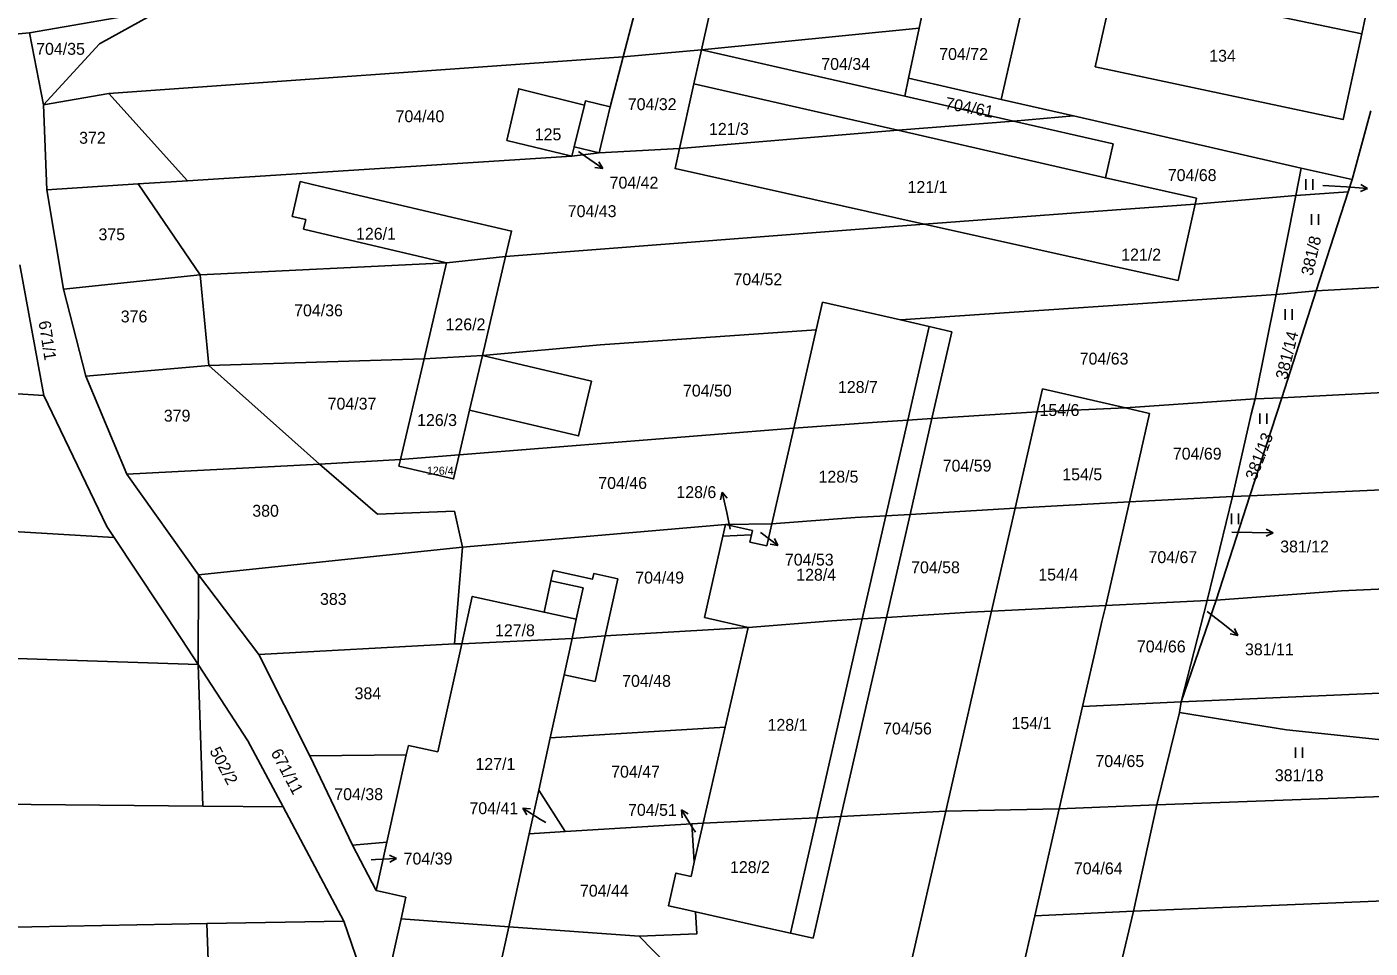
# Model space of a CAD drawing. Extents: x -747333 to -743907, y -1134120 to -1130051.
# Drawn here: x -746331.7 to -746140.1, y -1132458.3 to -1132327 of the extents above; entities that cross this region are included whole.
import ezdxf

# ---------------------------------------------------------------- set-up
doc = ezdxf.new("R2010")
doc.units = 0
for name, color, linetype in [('Hranice parcel', 7, 'Continuous'), ('Parcelní čísla', 7, 'Continuous'), ('Pop  PČ popisy', 7, 'Continuous'), ('Vnitřní kresba', 7, 'Continuous'), ('Značky kultur', 7, 'Continuous')]:
    doc.layers.add(name, color=color, linetype=linetype)

msp = doc.modelspace()

# ---------------------------------------------------------------- linework, layer by layer
at = {"layer": 'Hranice parcel'}
for p, q in [((-746243.49, -1132318.9), (-746246.67, -1132331.25)), ((-746204.45, -1132327.15), (-746203.36, -1132322.01)), ((-746312.67, -1132324.59), (-746331.35, -1132327.82)), ((-746331.35, -1132327.82), (-746338.47, -1132328.52)), ((-746329.35, -1132338.1), (-746331.35, -1132327.82)), ((-746235.51, -1132330.26), (-746204.45, -1132327.15)), ((-746205.97, -1132334.3), (-746204.45, -1132327.15)), ((-746320.03, -1132336.5), (-746246.67, -1132331.25)), ((-746246.67, -1132331.25), (-746248.52, -1132338.41)), ((-746235.51, -1132330.26), (-746246.67, -1132331.25)), ((-746206.52, -1132336.88), (-746235.51, -1132330.26)), ((-746206.52, -1132336.88), (-746205.97, -1132334.3)), ((-746192.75, -1132337.33), (-746205.97, -1132334.3)), ((-746329.35, -1132338.1), (-746320.03, -1132336.5)), ((-746308.82, -1132348.93), (-746320.03, -1132336.5)), ((-746191, -1132340.44), (-746206.52, -1132336.88)), ((-746192.75, -1132337.33), (-746182.47, -1132339.69)), ((-746328.92, -1132350.23), (-746329.35, -1132338.1)), ((-746250.11, -1132344.94), (-746248.52, -1132338.41)), ((-746140.02, -1132338.95), (-746142.7, -1132348.76)), ((-746191, -1132340.44), (-746182.47, -1132339.69)), ((-746182.47, -1132339.69), (-746149.96, -1132347.15)), ((-746254, -1132345.44), (-746250.11, -1132344.94)), ((-746250.11, -1132344.94), (-746238.64, -1132344.33)), ((-746308.82, -1132348.93), (-746254, -1132345.44)), ((-746149.96, -1132347.15), (-746150.75, -1132351.01)), ((-746149.96, -1132347.15), (-746142.7, -1132348.76)), ((-746315.89, -1132349.36), (-746308.82, -1132348.93)), ((-746142.7, -1132348.76), (-746143.26, -1132350.49)), ((-746328.92, -1132350.23), (-746315.89, -1132349.36)), ((-746326.5, -1132364.37), (-746328.92, -1132350.23)), ((-746307.02, -1132362.33), (-746315.89, -1132349.36)), ((-746150.75, -1132351.01), (-746165.1, -1132352.25)), ((-746150.75, -1132351.01), (-746153.53, -1132365.15)), ((-746143.26, -1132350.49), (-746150.75, -1132351.01)), ((-746147.85, -1132364.62), (-746143.26, -1132350.49)), ((-746167.52, -1132363.16), (-746165.1, -1132352.25)), ((-746165.1, -1132352.25), (-746164.91, -1132351.41)), ((-746263.46, -1132359.74), (-746203.77, -1132355.1)), ((-746271.87, -1132360.61), (-746307.02, -1132362.33)), ((-746271.87, -1132360.61), (-746275.09, -1132374.32)), ((-746271.87, -1132360.61), (-746263.46, -1132359.74)), ((-746266.76, -1132373.85), (-746263.46, -1132359.74)), ((-746332.76, -1132360.93), (-746329.31, -1132379.55)), ((-746326.5, -1132364.37), (-746307.02, -1132362.33)), ((-746305.8, -1132375.28), (-746307.02, -1132362.33)), ((-746323.35, -1132376.78), (-746326.5, -1132364.37)), ((-746218.25, -1132366.23), (-746219.16, -1132370.19)), ((-746207.14, -1132368.77), (-746218.25, -1132366.23)), ((-746207.14, -1132368.77), (-746153.53, -1132365.15)), ((-746153.53, -1132365.15), (-746156.53, -1132380)), ((-746153.53, -1132365.15), (-746147.85, -1132364.62)), ((-746147.85, -1132364.62), (-746152.75, -1132379.87)), ((-746219.16, -1132370.19), (-746222.36, -1132384.18)), ((-746202.64, -1132382.82), (-746199.81, -1132370.45)), ((-746275.09, -1132374.32), (-746266.76, -1132373.85)), ((-746329.31, -1132379.55), (-746393.81, -1132375.41)), ((-746323.35, -1132376.78), (-746305.8, -1132375.28)), ((-746305.8, -1132375.28), (-746275.09, -1132374.32)), ((-746290.02, -1132389.31), (-746305.8, -1132375.28)), ((-746275.09, -1132374.32), (-746278.43, -1132388.67)), ((-746317.5, -1132390.77), (-746323.35, -1132376.78)), ((-746186.88, -1132378.59), (-746187.63, -1132381.87)), ((-746175.05, -1132381.3), (-746186.88, -1132378.59)), ((-746187.63, -1132381.87), (-746175.05, -1132381.3)), ((-746175.05, -1132381.3), (-746156.53, -1132380)), ((-746171.59, -1132382.09), (-746175.05, -1132381.3)), ((-746157.28, -1132393.82), (-746152.75, -1132379.87)), ((-746152.75, -1132379.87), (-746156.53, -1132380)), ((-746205.77, -1132396.49), (-746202.64, -1132382.82)), ((-746187.63, -1132381.87), (-746202.64, -1132382.82)), ((-746187.63, -1132381.87), (-746190.78, -1132395.6)), ((-746174.48, -1132394.69), (-746171.59, -1132382.09)), ((-746222.36, -1132384.18), (-746270.08, -1132388)), ((-746222.36, -1132384.18), (-746225.48, -1132397.85)), ((-746317.5, -1132390.77), (-746290.02, -1132389.31)), ((-746290.02, -1132389.31), (-746278.43, -1132388.67)), ((-746278.43, -1132388.67), (-746278.67, -1132389.63)), ((-746278.43, -1132388.67), (-746270.08, -1132388)), ((-746307.24, -1132405.12), (-746317.5, -1132390.77)), ((-746190.78, -1132395.6), (-746174.48, -1132394.69)), ((-746177.86, -1132409.48), (-746174.48, -1132394.69)), ((-746159.75, -1132393.94), (-746174.48, -1132394.69)), ((-746159.75, -1132393.94), (-746163.39, -1132408.75)), ((-746162.11, -1132408.69), (-746157.28, -1132393.82)), ((-746157.28, -1132393.82), (-746159.75, -1132393.94)), ((-746319.27, -1132399.8), (-746393.81, -1132395.25)), ((-746209.13, -1132411.18), (-746205.77, -1132396.49)), ((-746190.78, -1132395.6), (-746205.77, -1132396.49)), ((-746190.78, -1132395.6), (-746194.14, -1132410.27)), ((-746269.62, -1132401.17), (-746232.07, -1132397.92)), ((-746232.07, -1132397.92), (-746232.46, -1132399.59)), ((-746232.07, -1132397.92), (-746225.48, -1132397.85)), ((-746228.24, -1132398.8), (-746232.07, -1132397.92)), ((-746228.36, -1132399.38), (-746228.24, -1132398.8)), ((-746225.48, -1132397.85), (-746226.2, -1132400.98)), ((-746232.46, -1132399.59), (-746235.08, -1132411.17)), ((-746232.46, -1132399.59), (-746228.36, -1132399.38)), ((-746228.61, -1132400.43), (-746228.36, -1132399.38)), ((-746226.2, -1132400.98), (-746228.61, -1132400.43)), ((-746307.24, -1132405.12), (-746269.62, -1132401.17)), ((-746270.74, -1132414.92), (-746269.62, -1132401.17)), ((-746307.32, -1132417.87), (-746307.24, -1132405.12)), ((-746307.24, -1132405.12), (-746298.66, -1132416.47)), ((-746249.25, -1132413.82), (-746247.47, -1132405.68)), ((-746194.14, -1132410.27), (-746200.67, -1132438.78)), ((-746177.86, -1132409.48), (-746194.14, -1132410.27)), ((-746163.39, -1132408.75), (-746177.86, -1132409.48)), ((-746167.1, -1132423.2), (-746162.11, -1132408.69)), ((-746163.39, -1132408.75), (-746167.1, -1132423.2)), ((-746162.11, -1132408.69), (-746163.39, -1132408.75)), ((-746235.08, -1132411.17), (-746228.86, -1132412.6)), ((-746215.62, -1132439.55), (-746209.13, -1132411.18)), ((-746250.68, -1132420.32), (-746249.25, -1132413.82)), ((-746228.86, -1132412.6), (-746249.25, -1132413.82)), ((-746228.86, -1132412.6), (-746232.13, -1132426.83)), ((-746394.09, -1132415.09), (-746307.32, -1132417.87)), ((-746298.66, -1132416.47), (-746270.74, -1132414.92)), ((-746269.71, -1132414.92), (-746273.12, -1132430.35)), ((-746269.71, -1132414.92), (-746270.74, -1132414.92)), ((-746306.63, -1132438.08), (-746307.32, -1132417.87)), ((-746298.66, -1132416.47), (-746291.38, -1132430.89)), ((-746257.1, -1132428.36), (-746255.12, -1132419.34)), ((-746255.12, -1132419.34), (-746250.68, -1132420.32)), ((-746181.17, -1132423.88), (-746180.79, -1132422.22)), ((-746167.1, -1132423.2), (-746181.17, -1132423.88)), ((-746167.1, -1132423.2), (-746167.33, -1132424.75)), ((-746184.48, -1132438.45), (-746181.17, -1132423.88)), ((-746167.33, -1132424.75), (-746170.57, -1132437.88)), ((-746232.13, -1132426.83), (-746257.1, -1132428.36)), ((-746232.13, -1132426.83), (-746235.26, -1132440.49)), ((-746277.32, -1132429.43), (-746277.62, -1132430.78)), ((-746273.12, -1132430.35), (-746277.32, -1132429.43)), ((-746258.73, -1132435.79), (-746257.1, -1132428.36)), ((-746291.38, -1132430.89), (-746277.62, -1132430.78)), ((-746291.38, -1132430.89), (-746285.28, -1132443.62)), ((-746277.62, -1132430.78), (-746280.38, -1132443.23)), ((-746170.57, -1132437.88), (-746081.14, -1132434.64)), ((-746306.63, -1132438.08), (-746394.38, -1132437.22)), ((-746260.09, -1132442), (-746258.73, -1132435.79)), ((-746254.98, -1132441.69), (-746258.73, -1132435.79)), ((-746295.18, -1132438.19), (-746306.63, -1132438.08)), ((-746286.51, -1132454.45), (-746295.18, -1132438.19)), ((-746200.67, -1132438.78), (-746215.62, -1132439.55)), ((-746200.67, -1132438.78), (-746211.18, -1132484.59)), ((-746184.48, -1132438.45), (-746200.67, -1132438.78)), ((-746187.96, -1132453.69), (-746184.48, -1132438.45)), ((-746170.57, -1132437.88), (-746184.48, -1132438.45)), ((-746170.57, -1132437.88), (-746173.89, -1132453.04)), ((-746236.91, -1132440.59), (-746254.98, -1132441.69)), ((-746236.91, -1132440.59), (-746235.26, -1132440.49)), ((-746236.54, -1132446.07), (-746236.91, -1132440.59)), ((-746235.26, -1132440.49), (-746236.54, -1132446.07)), ((-746219.59, -1132456.9), (-746215.62, -1132439.55)), ((-746263.02, -1132455.29), (-746260.09, -1132442)), ((-746260.09, -1132442), (-746254.98, -1132441.69)), ((-746285.28, -1132443.62), (-746280.38, -1132443.23)), ((-746285.28, -1132443.62), (-746281.91, -1132450.11)), ((-746280.38, -1132443.23), (-746281.91, -1132450.11)), ((-746236.54, -1132446.07), (-746236.99, -1132448.11)), ((-746281.91, -1132450.11), (-746277.69, -1132451.04)), ((-746083.22, -1132449.3), (-746173.89, -1132453.04)), ((-746277.69, -1132451.04), (-746278.37, -1132454.12)), ((-746306.06, -1132454.82), (-746286.51, -1132454.45)), ((-746281.65, -1132468.73), (-746286.51, -1132454.45)), ((-746278.37, -1132454.12), (-746281.65, -1132468.73)), ((-746263.02, -1132455.29), (-746278.37, -1132454.12)), ((-746238.04, -1132452.77), (-746236.36, -1132453.14)), ((-746236.36, -1132453.14), (-746226.89, -1132455.27)), ((-746195.82, -1132488.1), (-746187.96, -1132453.69)), ((-746173.89, -1132453.04), (-746187.96, -1132453.69)), ((-746173.89, -1132453.04), (-746183.99, -1132495.14)), ((-746349.28, -1132455.63), (-746306.06, -1132454.82)), ((-746305.4, -1132474), (-746306.06, -1132454.82)), ((-746264.05, -1132460), (-746263.02, -1132455.29)), ((-746263.02, -1132455.29), (-746244.39, -1132456.6)), ((-746234.32, -1132466.9), (-746244.39, -1132456.6))]:
    msp.add_line(p, q, dxfattribs=at)
for points in [[(-746235.51, -1132330.26), (-746233.35, -1132320.43), (-746234.16, -1132317.42)], [(-746176.65, -1132320.68), (-746179.36, -1132332.68), (-746143.97, -1132340.17), (-746141.34, -1132327.96), (-746140.26, -1132322.97), (-746162.74, -1132318.47), (-746162.95, -1132319.47), (-746171.73, -1132317.69), (-746172.66, -1132321.47), (-746176.65, -1132320.68)], [(-746203.36, -1132322.01), (-746189.95, -1132325.07), (-746192.75, -1132337.33)], [(-746312.67, -1132324.59), (-746321.38, -1132329.41), (-746329.35, -1132338.1)], [(-746238.64, -1132344.33), (-746236.59, -1132335.09), (-746235.51, -1132330.26)], [(-746248.52, -1132338.41), (-746252.07, -1132337.54), (-746252.22, -1132338.13), (-746261.58, -1132335.81), (-746263.26, -1132343.18), (-746254, -1132345.44)], [(-746238.64, -1132344.33), (-746207.53, -1132341.69), (-746191, -1132340.44)], [(-746164.91, -1132351.41), (-746177.89, -1132348.53), (-746176.81, -1132343.67), (-746191, -1132340.44)], [(-746254, -1132345.44), (-746253.67, -1132344.08), (-746250.11, -1132344.94)], [(-746238.64, -1132344.33), (-746239.28, -1132347.2), (-746203.77, -1132355.1)], [(-746263.46, -1132359.74), (-746262.61, -1132356.11), (-746270.39, -1132354.29), (-746290.8, -1132349.51), (-746292.74, -1132349.05), (-746293.9, -1132354.01), (-746291.96, -1132354.46), (-746292.28, -1132355.82), (-746271.87, -1132360.61)], [(-746203.77, -1132355.1), (-746178.95, -1132353.27), (-746165.1, -1132352.25)], [(-746203.77, -1132355.1), (-746180.51, -1132360.27), (-746167.52, -1132363.16)], [(-746147.85, -1132364.62), (-746096.79, -1132361.81), (-746048.74, -1132358.8)], [(-746219.16, -1132370.19), (-746249.96, -1132372.31), (-746266.76, -1132373.85)], [(-746199.81, -1132370.45), (-746203.03, -1132369.71), (-746207.14, -1132368.77)], [(-746270.08, -1132388), (-746268.59, -1132381.65), (-746253.04, -1132385.29), (-746251.21, -1132377.49), (-746266.76, -1132373.85)], [(-746152.75, -1132379.87), (-746113.78, -1132377.83), (-746055.32, -1132374.7)], [(-746329.31, -1132379.55), (-746320.33, -1132398.2), (-746319.27, -1132399.8)], [(-746156.53, -1132380), (-746157.1, -1132382.21), (-746159.75, -1132393.94)], [(-746222.36, -1132384.18), (-746210.47, -1132383.32), (-746206.08, -1132383.04), (-746202.64, -1132382.82)], [(-746269.62, -1132401.17), (-746270.76, -1132396.03), (-746281.75, -1132396.46), (-746290.02, -1132389.31)], [(-746278.67, -1132389.63), (-746270.88, -1132391.42), (-746270.08, -1132388)], [(-746060.62, -1132389.28), (-746101.87, -1132391.32), (-746157.28, -1132393.82)], [(-746225.48, -1132397.85), (-746213.58, -1132396.95), (-746209.21, -1132396.69), (-746205.77, -1132396.49)], [(-746319.27, -1132399.8), (-746309.63, -1132414.33), (-746307.32, -1132417.87)], [(-746247.47, -1132405.68), (-746250.89, -1132404.93), (-746251.06, -1132405.71), (-746256.67, -1132404.48), (-746256.99, -1132405.94), (-746257.98, -1132410.43), (-746268.22, -1132408.18), (-746269.71, -1132414.92)], [(-746065.82, -1132403.81), (-746144.23, -1132407.39), (-746162.11, -1132408.69)], [(-746194.14, -1132410.27), (-746197.15, -1132410.42), (-746209.13, -1132411.18)], [(-746180.79, -1132422.22), (-746179.4, -1132416.21), (-746178.39, -1132411.74), (-746177.86, -1132409.48)], [(-746209.13, -1132411.18), (-746212.58, -1132411.39), (-746216.94, -1132411.67), (-746228.86, -1132412.6)], [(-746249.25, -1132413.82), (-746253.98, -1132414.19), (-746269.71, -1132414.92)], [(-746295.18, -1132438.19), (-746300.21, -1132428.75), (-746307.32, -1132417.87)], [(-746167.1, -1132423.2), (-746121.36, -1132421.23), (-746071.19, -1132418.69)], [(-746081.14, -1132434.64), (-746152.06, -1132427.18), (-746167.33, -1132424.75)], [(-746215.62, -1132439.55), (-746219.07, -1132439.73), (-746223.39, -1132439.95), (-746235.26, -1132440.49)], [(-746236.99, -1132448.11), (-746239.16, -1132447.62), (-746240.2, -1132452.29), (-746238.04, -1132452.77)], [(-746244.39, -1132456.6), (-746236.2, -1132456.28), (-746236.36, -1132453.14)], [(-746226.89, -1132455.27), (-746222.84, -1132456.18), (-746219.59, -1132456.9)]]:
    msp.add_lwpolyline(points, dxfattribs=at)
at = {"layer": 'Pop  PČ popisy'}
for p, q in [((-746253.08, -1132344.75), (-746252.07, -1132345.47)), ((-746252.07, -1132345.47), (-746249.612, -1132347.191)), ((-746249.612, -1132347.191), (-746250.719, -1132347.027)), ((-746249.612, -1132347.191), (-746250.145, -1132346.207)), ((-746146.88, -1132349.58), (-746143.49, -1132349.8)), ((-746143.49, -1132349.8), (-746140.496, -1132350.009)), ((-746140.496, -1132350.009), (-746141.53, -1132350.439)), ((-746140.496, -1132350.009), (-746141.46, -1132349.44)), ((-746232.544, -1132393.305), (-746232.826, -1132394.388)), ((-746231.92, -1132396.24), (-746232.544, -1132393.305)), ((-746232.544, -1132393.305), (-746231.846, -1132394.18)), ((-746231.41, -1132398.59), (-746231.92, -1132396.24)), ((-746153.969, -1132399.102), (-746154.962, -1132398.584)), ((-746227.09, -1132399.07), (-746227.01, -1132399.13)), ((-746227.01, -1132399.13), (-746224.613, -1132400.936)), ((-746224.613, -1132400.936), (-746225.714, -1132400.733)), ((-746224.613, -1132400.936), (-746225.112, -1132399.933)), ((-746159.89, -1132399.02), (-746156.97, -1132399.05)), ((-746156.97, -1132399.05), (-746153.969, -1132399.102)), ((-746153.969, -1132399.102), (-746154.98, -1132399.586)), ((-746163.38, -1132410.34), (-746161.36, -1132411.9)), ((-746161.36, -1132411.9), (-746158.995, -1132413.748)), ((-746158.995, -1132413.748), (-746160.093, -1132413.526)), ((-746158.995, -1132413.748), (-746159.476, -1132412.736)), ((-746258.46, -1132439.96), (-746261.005, -1132438.37)), ((-746261.005, -1132438.37), (-746259.89, -1132438.476)), ((-746261.005, -1132438.37), (-746260.421, -1132439.325)), ((-746236.78, -1132441.15), (-746238.37, -1132438.605)), ((-746238.37, -1132438.605), (-746237.415, -1132439.189)), ((-746238.37, -1132438.605), (-746238.264, -1132439.72)), ((-746257.72, -1132440.42), (-746258.46, -1132439.96)), ((-746236.39, -1132441.77), (-746236.78, -1132441.15)), ((-746282.63, -1132445.72), (-746282, -1132445.69)), ((-746282, -1132445.69), (-746279.003, -1132445.533)), ((-746279.003, -1132445.533), (-746280.029, -1132445.085)), ((-746279.003, -1132445.533), (-746279.977, -1132446.085))]:
    msp.add_line(p, q, dxfattribs=at)
at = {"layer": 'Vnitřní kresba'}
for p, q in [((-746163.76, -1132323.31), (-746141.34, -1132327.96)), ((-746236.59, -1132335.09), (-746207.53, -1132341.69)), ((-746252.22, -1132338.13), (-746253.67, -1132344.08)), ((-746207.53, -1132341.69), (-746177.89, -1132348.53)), ((-746206.08, -1132383.04), (-746203.03, -1132369.71)), ((-746268.59, -1132381.65), (-746266.76, -1132373.85)), ((-746209.21, -1132396.69), (-746206.08, -1132383.04)), ((-746212.58, -1132411.39), (-746209.21, -1132396.69)), ((-746256.99, -1132405.94), (-746252.39, -1132406.95)), ((-746252.39, -1132406.95), (-746253.38, -1132411.44)), ((-746253.38, -1132411.44), (-746257.98, -1132410.43)), ((-746253.38, -1132411.44), (-746253.98, -1132414.19)), ((-746219.07, -1132439.73), (-746212.58, -1132411.39)), ((-746253.98, -1132414.19), (-746255.12, -1132419.34)), ((-746222.84, -1132456.18), (-746219.07, -1132439.73))]:
    msp.add_line(p, q, dxfattribs=at)
at = {"layer": 'Značky kultur'}
for p, q in [((-746149.301, -1132350.2), (-746149.301, -1132348.7)), ((-746148.3, -1132350.2), (-746148.3, -1132348.7)), ((-746148.491, -1132355.19), (-746148.491, -1132353.69)), ((-746147.49, -1132355.19), (-746147.49, -1132353.69)), ((-746152.281, -1132368.73), (-746152.281, -1132367.23)), ((-746151.28, -1132368.73), (-746151.28, -1132367.23)), ((-746155.891, -1132383.59), (-746155.891, -1132382.09)), ((-746154.89, -1132383.59), (-746154.89, -1132382.09)), ((-746159.911, -1132397.88), (-746159.911, -1132396.38)), ((-746158.91, -1132397.88), (-746158.91, -1132396.38)), ((-746150.781, -1132431.21), (-746150.781, -1132429.71)), ((-746149.78, -1132431.21), (-746149.78, -1132429.71))]:
    msp.add_line(p, q, dxfattribs=at)

# ---------------------------------------------------------------- texts
at = {"layer": 'Parcelní čísla'}
for s, height, p in [('704/35', 1.7, (-746330.42, -1132330.97)), ('704/72', 1.7, (-746201.605, -1132331.71)), ('704/34', 1.7, (-746218.425, -1132333.13)), ('134', 1.7, (-746163.09, -1132331.96)), ('704/32', 1.7, (-746246.025, -1132338.86)), ('704/40', 1.7, (-746279.15, -1132340.58)), ('125', 1.7, (-746259.3, -1132343.16)), ('121/3', 1.7, (-746234.45, -1132342.38)), ('372', 1.7, (-746324.29, -1132343.65)), ('704/68', 1.7, (-746169, -1132348.97)), ('704/42', 1.7, (-746248.62, -1132350.043)), ('121/1', 1.7, (-746206.12, -1132350.66)), ('704/43', 1.7, (-746254.59, -1132354.11)), ('375', 1.7, (-746321.53, -1132357.41)), ('126/1', 1.7, (-746284.79, -1132357.33)), ('121/2', 1.7, (-746175.65, -1132360.3)), ('704/52', 1.7, (-746230.95, -1132363.82)), ('376', 1.7, (-746318.35, -1132369.12)), ('704/36', 1.7, (-746293.62, -1132368.25)), ('126/2', 1.7, (-746272.02, -1132370.25)), ('704/63', 1.7, (-746181.57, -1132375.13)), ('128/7', 1.7, (-746216.05, -1132379.17)), ('704/37', 1.7, (-746288.84, -1132381.55)), ('704/50', 1.7, (-746238.16, -1132379.69)), ('379', 1.7, (-746312.21, -1132383.26)), ('154/6', 1.7, (-746187.303, -1132382.46)), ('126/3', 1.7, (-746276.08, -1132383.89)), ('704/69', 1.7, (-746168.28, -1132388.68)), ('704/59', 1.7, (-746201.11, -1132390.39)), ('126/4', 1.14, (-746274.68, -1132390.83)), ('704/46', 1.7, (-746250.24, -1132392.86)), ('128/5', 1.7, (-746218.82, -1132391.96)), ('154/5', 1.7, (-746184.05, -1132391.63)), ('128/6', 1.7, (-746239.096, -1132394.16)), ('380', 1.7, (-746299.59, -1132396.82)), ('381/12', 1.7, (-746152.97, -1132401.913)), ('704/53', 1.7, (-746223.62, -1132403.783)), ('704/67', 1.7, (-746171.75, -1132403.43)), ('704/49', 1.7, (-746244.96, -1132406.34)), ('128/4', 1.7, (-746222, -1132405.94)), ('704/58', 1.7, (-746205.61, -1132404.88)), ('154/4', 1.7, (-746187.47, -1132405.91)), ('383', 1.7, (-746289.93, -1132409.39)), ('127/8', 1.7, (-746264.97, -1132413.86)), ('704/66', 1.7, (-746173.41, -1132416.16)), ('381/11', 1.7, (-746157.99, -1132416.573)), ('704/48', 1.7, (-746246.83, -1132421.07)), ('384', 1.7, (-746285, -1132422.84)), ('128/1', 1.7, (-746226.09, -1132427.34)), ('154/1', 1.7, (-746191.29, -1132427.09)), ('704/56', 1.7, (-746209.61, -1132427.86)), ('127/1', 1.7, (-746267.76, -1132432.91)), ('704/65', 1.7, (-746179.32, -1132432.5)), ('704/47', 1.7, (-746248.4, -1132434.02)), ('381/18', 1.7, (-746153.73, -1132434.52)), ('704/38', 1.7, (-746287.89, -1132437.22)), ('704/41', 1.7, (-746268.611, -1132439.22)), ('704/51', 1.7, (-746245.991, -1132439.46)), ('704/39', 1.7, (-746278, -1132446.4)), ('128/2', 1.7, (-746231.45, -1132447.62)), ('704/64', 1.7, (-746182.4, -1132447.8)), ('704/44', 1.7, (-746252.85, -1132450.98))]:
    msp.add_text(s, height=height, dxfattribs=at).set_placement(p)
for s, rotation, p in [('704/61', 349, (-746200.872, -1132338.644)), ('381/8', 77, (-746148.371, -1132362.571)), ('671/1', 279, (-746330.089, -1132369.012)), ('381/14', 76, (-746152.025, -1132377.375)), ('381/13', 69, (-746156.426, -1132391.754)), ('502/2', 298, (-746305.742, -1132430.19)), ('671/11', 298, (-746297.002, -1132430.45))]:
    msp.add_text(s, height=1.7, rotation=rotation, dxfattribs=at).set_placement(p)

doc.saveas('drawing.dxf')
